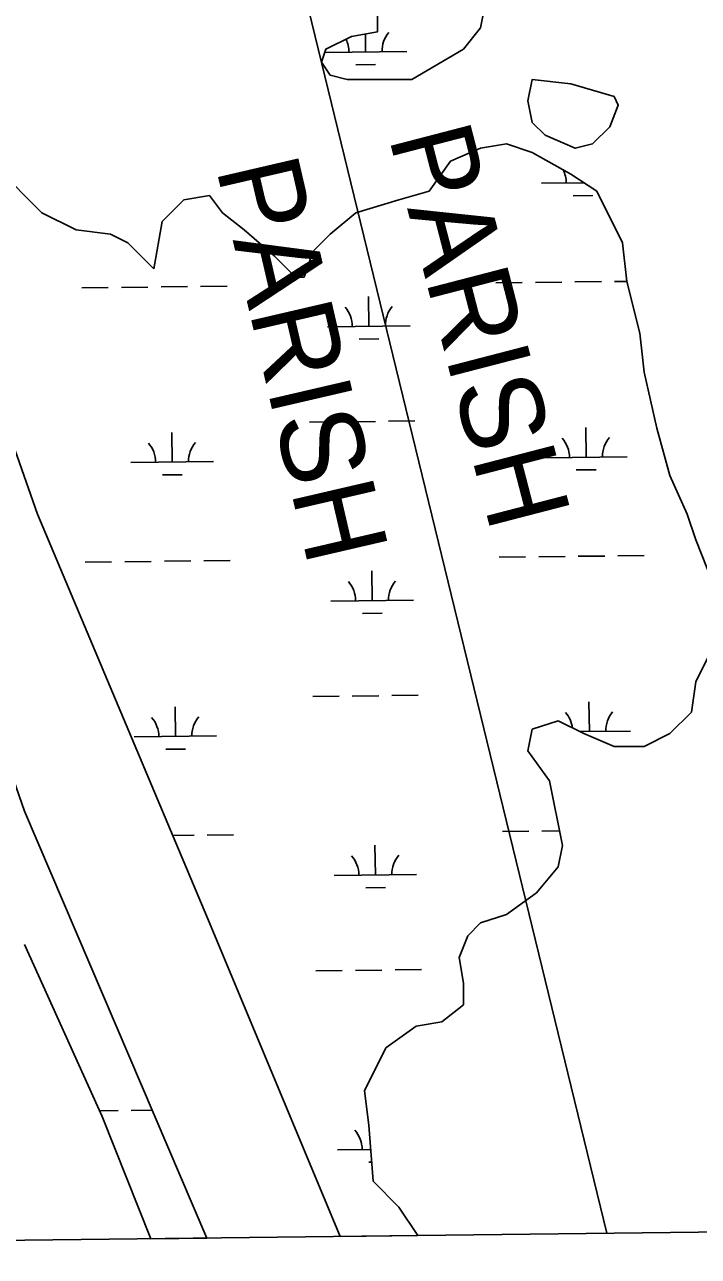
# Model space of a CAD drawing. Extents: x 3694830 to 3732949, y 415201 to 440970.
# Drawn here: x 3700698 to 3701515, y 420616 to 422110 of the extents above; entities that cross this region are included whole.
import ezdxf

# ---------------------------------------------------------------- set-up
doc = ezdxf.new("R2010")
doc.units = 0
for name, color, linetype in [('V-GRID-FRAM', 7, 'Continuous'), ('V-TOPO-BNDY', 7, 'Continuous'), ('V-TOPO-GNAM-IDEN', 7, 'Continuous'), ('V-TOPO-SHOR', 7, 'Continuous'), ('V-WETL-SWMP', 7, 'Continuous')]:
    doc.layers.add(name, color=color, linetype=linetype)

msp = doc.modelspace()

# ---------------------------------------------------------------- linework, layer by layer
at = {"layer": 'V-GRID-FRAM'}
msp.add_lwpolyline([(3698844.7, 438797.5), (3730590.8, 439176.2), (3730815.6, 420995.1), (3699053.6, 420616.3), (3698844.7, 438797.5)], dxfattribs=at)
at = {"layer": 'V-TOPO-BNDY'}
msp.add_line((3701404.1, 420644.3), (3699327.4, 429171.8), dxfattribs=at)
at = {"layer": 'V-TOPO-SHOR'}
for p, q in [((3700714, 421516.3), (3700537.1, 422017.2)), ((3701214.7, 421944.3), (3701251.2, 421959.9)), ((3701251.2, 421959.9), (3701282.5, 421965.2)), ((3701282.5, 421965.2), (3701313.8, 421954.7)), ((3701188.6, 421907.7), (3701214.7, 421944.3)), ((3701313.8, 421954.7), (3701360.7, 421928.6)), ((3700661.8, 421939.1), (3700719.2, 421881.7)), ((3701360.7, 421928.6), (3701392, 421907.7)), ((3700865.2, 421871.2), (3700891.3, 421897.3)), ((3700891.3, 421897.3), (3700922.6, 421902.5)), ((3700922.6, 421902.5), (3700938.2, 421881.7)), ((3701099.9, 421881.7), (3701152.1, 421897.3)), ((3701152.1, 421897.3), (3701188.6, 421907.7)), ((3701392, 421907.7), (3701423.3, 421845.1)), ((3700719.2, 421881.7), (3700760.9, 421860.8)), ((3700938.2, 421881.7), (3700964.3, 421860.8)), ((3701068.6, 421855.6), (3701099.9, 421881.7)), ((3700854.8, 421813.8), (3700865.2, 421871.2)), ((3700760.9, 421860.8), (3700802.6, 421855.6)), ((3700802.6, 421855.6), (3700823.5, 421845.1)), ((3700964.3, 421860.8), (3701000.8, 421829.5)), ((3701047.8, 421834.7), (3701068.6, 421855.6)), ((3700823.5, 421845.1), (3700854.8, 421813.8)), ((3701423.3, 421845.1), (3701428.5, 421798.2)), ((3701000.8, 421829.5), (3701026.9, 421803.4)), ((3701037.3, 421803.4), (3701047.8, 421834.7)), ((3701026.9, 421803.4), (3701037.3, 421803.4)), ((3701428.5, 421798.2), (3701444.2, 421735.5)), ((3701444.2, 421735.5), (3701449.4, 421688.6)), ((3701449.4, 421688.6), (3701465, 421620.7)), ((3700531.4, 421631.1), (3700698.3, 421156.2)), ((3701465, 421620.7), (3701480.7, 421563.3)), ((3701480.7, 421563.3), (3701501.5, 421516.3)), ((3700922.6, 421020.5), (3700714, 421516.3)), ((3701501.5, 421516.3), (3701512, 421485)), ((3701512, 421485), (3701532.8, 421432.8)), ((3701532.8, 421354.5), (3701512, 421312.8)), ((3701512, 421312.8), (3701506.8, 421276.3)), ((3701506.8, 421276.3), (3701480.7, 421250.2)), ((3701313.8, 421255.4), (3701308.6, 421229.3)), ((3701345.1, 421265.8), (3701313.8, 421255.4)), ((3701376.4, 421250.2), (3701345.1, 421265.8)), ((3701412.9, 421234.5), (3701376.4, 421250.2)), ((3701480.7, 421250.2), (3701449.4, 421234.5)), ((3701308.6, 421229.3), (3701334.6, 421192.7)), ((3701449.4, 421234.5), (3701412.9, 421234.5)), ((3701334.6, 421192.7), (3701350.3, 421114.5)), ((3700698.3, 421156.2), (3700919.3, 420638.5)), ((3701350.3, 421114.5), (3701345.1, 421088.4)), ((3701345.1, 421088.4), (3701319, 421057.1)), ((3701319, 421057.1), (3701282.5, 421031)), ((3701282.5, 421031), (3701251.2, 421020.5)), ((3701080.9, 420640.5), (3700922.6, 421020.5)), ((3701251.2, 421020.5), (3701235.5, 421004.9)), ((3701235.5, 421004.9), (3701225.1, 420978.8)), ((3700792.2, 420785.7), (3700698.3, 420994.4)), ((3701225.1, 420978.8), (3701230.3, 420947.5)), ((3701230.3, 420947.5), (3701230.3, 420921.4)), ((3701230.3, 420921.4), (3701204.2, 420900.5)), ((3701172.9, 420895.3), (3701136.4, 420869.2)), ((3701204.2, 420900.5), (3701172.9, 420895.3)), ((3701136.4, 420869.2), (3701110.4, 420817)), ((3701110.4, 420817), (3701115.6, 420775.2)), ((3700851.3, 420637.7), (3700792.2, 420785.7)), ((3701115.6, 420775.2), (3701120.8, 420707.4)), ((3701120.8, 420707.4), (3701152.1, 420676.1)), ((3701152.1, 420676.1), (3701175.1, 420641.6))]:
    msp.add_line(p, q, dxfattribs=at)
for points in [[(3701167.7, 422043.4), (3701089.5, 422043.4), (3701068.6, 422048.7), (3701058.2, 422064.3), (3701063.4, 422080), (3701094.7, 422095.6), (3701126, 422100.9), (3701126, 422147.8), (3701141.6, 422168.7), (3701167.7, 422179.1), (3701199, 422179.1), (3701251.2, 422158.3), (3701256.4, 422132.2), (3701251.2, 422106.1), (3701230.3, 422080)], [(3701360.7, 422038.2), (3701412.9, 422022.6), (3701418.1, 422012.1), (3701407.7, 421986), (3701386.8, 421965.2), (3701365.9, 421959.9), (3701329.4, 421975.6), (3701313.8, 421991.3), (3701308.6, 422017.3), (3701313.8, 422043.4)]]:
    msp.add_lwpolyline(points, close=True, dxfattribs=at)
at = {"layer": 'V-WETL-SWMP'}
for p, q in [((3701111.6, 422076.7), (3701111.4, 422098.4)), ((3701062.1, 422076.1), (3701161.6, 422077.3)), ((3701099.8, 422061.1), (3701123.8, 422061.4)), ((3700714, 421516.3), (3700537.1, 422017.2)), ((3701214.7, 421944.3), (3701251.2, 421959.9)), ((3701251.2, 421959.9), (3701282.5, 421965.2)), ((3701282.5, 421965.2), (3701313.8, 421954.7)), ((3701188.6, 421907.7), (3701214.7, 421944.3)), ((3701313.8, 421954.7), (3701360.7, 421928.6)), ((3700661.8, 421939.1), (3700719.2, 421881.7)), ((3701360.7, 421928.6), (3701392, 421907.7)), ((3701325, 421917.4), (3701376.6, 421918)), ((3701375, 421918), (3701375, 421919.1)), ((3700865.2, 421871.2), (3700891.3, 421897.3)), ((3700891.3, 421897.3), (3700922.6, 421902.5)), ((3700922.6, 421902.5), (3700938.2, 421881.7)), ((3701099.9, 421881.7), (3701152.1, 421897.3)), ((3701152.1, 421897.3), (3701188.6, 421907.7)), ((3701363.2, 421902.4), (3701387.2, 421902.7)), ((3701392, 421907.7), (3701423.3, 421845.1)), ((3700719.2, 421881.7), (3700760.9, 421860.8)), ((3700938.2, 421881.7), (3700964.3, 421860.8)), ((3701068.6, 421855.6), (3701099.9, 421881.7)), ((3700854.8, 421813.8), (3700865.2, 421871.2)), ((3700760.9, 421860.8), (3700802.6, 421855.6)), ((3700802.6, 421855.6), (3700823.5, 421845.1)), ((3700964.3, 421860.8), (3701000.8, 421829.5)), ((3701047.8, 421834.7), (3701068.6, 421855.6)), ((3700823.5, 421845.1), (3700854.8, 421813.8)), ((3701423.3, 421845.1), (3701428.5, 421798.2)), ((3701000.8, 421829.5), (3701026.9, 421803.4)), ((3701037.3, 421803.4), (3701047.8, 421834.7)), ((3700767.7, 421790.7), (3700799.7, 421791)), ((3700815.7, 421791.2), (3700847.7, 421791.6)), ((3700863.7, 421791.8), (3700895.7, 421792.2)), ((3700911.7, 421792.4), (3700943.7, 421792.8)), ((3701026.9, 421803.4), (3701037.3, 421803.4)), ((3701269.6, 421796.6), (3701301.6, 421797)), ((3701317.6, 421797.2), (3701349.6, 421797.6)), ((3701365.6, 421797.8), (3701397.6, 421798.2)), ((3701413.6, 421798.4), (3701428.5, 421798.5)), ((3701428.5, 421798.2), (3701444.2, 421735.5)), ((3701115.6, 421744.1), (3701115.2, 421780.1)), ((3701065.6, 421743.5), (3701165.6, 421744.7)), ((3701444.2, 421735.5), (3701449.4, 421688.6)), ((3701103.8, 421728.5), (3701127.8, 421728.8)), ((3701449.4, 421688.6), (3701465, 421620.7)), ((3700531.4, 421631.1), (3700698.3, 421156.2)), ((3701043.6, 421627.8), (3701075.6, 421628.1)), ((3701091.6, 421628.3), (3701123.6, 421628.7)), ((3701139.6, 421628.9), (3701171.6, 421629.3)), ((3700877.1, 421579.3), (3700876.7, 421615.3)), ((3701379, 421585.3), (3701378.6, 421621.3)), ((3701465, 421620.7), (3701480.7, 421563.3)), ((3701329, 421584.7), (3701429, 421585.9)), ((3700827.1, 421578.7), (3700927.1, 421579.9)), ((3701367.2, 421569.8), (3701391.2, 421570)), ((3700865.3, 421563.8), (3700889.3, 421564.1)), ((3701480.7, 421563.3), (3701501.5, 421516.3)), ((3700922.6, 421020.5), (3700714, 421516.3)), ((3701501.5, 421516.3), (3701512, 421485)), ((3701512, 421485), (3701532.8, 421432.8)), ((3701273.6, 421464), (3701305.6, 421464.4)), ((3701321.6, 421464.6), (3701353.6, 421464.9)), ((3701369.6, 421465.1), (3701401.6, 421465.5)), ((3701417.6, 421465.7), (3701449.6, 421466.1)), ((3700771.7, 421458), (3700803.7, 421458.4)), ((3700819.7, 421458.6), (3700851.7, 421459)), ((3700867.7, 421459.1), (3700899.7, 421459.5)), ((3700915.7, 421459.7), (3700947.7, 421460.1)), ((3701119.6, 421411.4), (3701119.2, 421447.4)), ((3701069.6, 421410.8), (3701169.6, 421412)), ((3701107.8, 421395.8), (3701131.8, 421396.1)), ((3701532.8, 421354.5), (3701512, 421312.8)), ((3701512, 421312.8), (3701506.8, 421276.3)), ((3701047.6, 421295.1), (3701079.6, 421295.5)), ((3701095.6, 421295.7), (3701127.6, 421296.1)), ((3701143.6, 421296.3), (3701175.6, 421296.6)), ((3701383, 421252.7), (3701382.5, 421288.7)), ((3700881.1, 421246.7), (3700880.7, 421282.7)), ((3701506.8, 421276.3), (3701480.7, 421250.2)), ((3701313.8, 421255.4), (3701308.6, 421229.3)), ((3701345.1, 421265.8), (3701313.8, 421255.4)), ((3701376.4, 421250.2), (3701345.1, 421265.8)), ((3701371.6, 421252.5), (3701432.9, 421253.3)), ((3700831.1, 421246.1), (3700931.1, 421247.3)), ((3701412.9, 421234.5), (3701376.4, 421250.2)), ((3701480.7, 421250.2), (3701449.4, 421234.5)), ((3700869.3, 421231.1), (3700893.3, 421231.4)), ((3701308.6, 421229.3), (3701334.6, 421192.7)), ((3701449.4, 421234.5), (3701412.9, 421234.5)), ((3701334.6, 421192.7), (3701350.3, 421114.5)), ((3700698.3, 421156.2), (3700919.3, 420638.5)), ((3700878, 421126.6), (3700903.7, 421126.9)), ((3700919.7, 421127.1), (3700951.7, 421127.5)), ((3701277.5, 421131.3), (3701309.5, 421131.7)), ((3701325.5, 421131.9), (3701346.7, 421132.2)), ((3701123.6, 421078.8), (3701123.1, 421114.8)), ((3701350.3, 421114.5), (3701345.1, 421088.4)), ((3701073.6, 421078.2), (3701173.6, 421079.4)), ((3701345.1, 421088.4), (3701319, 421057.1)), ((3701111.8, 421063.2), (3701135.8, 421063.5)), ((3701319, 421057.1), (3701282.5, 421031)), ((3701282.5, 421031), (3701251.2, 421020.5)), ((3701080.9, 420640.5), (3700922.6, 421020.5)), ((3701251.2, 421020.5), (3701235.5, 421004.9)), ((3701235.5, 421004.9), (3701225.1, 420978.8)), ((3700792.2, 420785.7), (3700698.3, 420994.4)), ((3701225.1, 420978.8), (3701230.3, 420947.5)), ((3701051.5, 420962.5), (3701083.5, 420962.8)), ((3701099.5, 420963), (3701131.5, 420963.4)), ((3701147.5, 420963.6), (3701179.5, 420964)), ((3701230.3, 420947.5), (3701230.3, 420921.4)), ((3701230.3, 420921.4), (3701204.2, 420900.5)), ((3701172.9, 420895.3), (3701136.4, 420869.2)), ((3701204.2, 420900.5), (3701172.9, 420895.3)), ((3701136.4, 420869.2), (3701110.4, 420817)), ((3701110.4, 420817), (3701115.6, 420775.2)), ((3700789, 420792.8), (3700811.6, 420793.1)), ((3700827.6, 420793.3), (3700853.1, 420793.6)), ((3700851.3, 420637.7), (3700792.2, 420785.7)), ((3701115.6, 420775.2), (3701120.8, 420707.4)), ((3701077.5, 420745.5), (3701117.8, 420746)), ((3701115.7, 420730.5), (3701119, 420730.6)), ((3701120.8, 420707.4), (3701152.1, 420676.1)), ((3701152.1, 420676.1), (3701175.1, 420641.6)), ((3701175.1, 420641.6), (3701080.9, 420640.5)), ((3700919.3, 420638.5), (3700851.3, 420637.7))]:
    msp.add_line(p, q, dxfattribs=at)
for points in [[(3701167.7, 422043.4), (3701089.5, 422043.4), (3701068.6, 422048.7), (3701058.2, 422064.3), (3701063.4, 422080), (3701094.7, 422095.6), (3701126, 422100.9), (3701126, 422147.8), (3701141.6, 422168.7), (3701167.7, 422179.1), (3701199, 422179.1), (3701251.2, 422158.3), (3701256.4, 422132.2), (3701251.2, 422106.1), (3701230.3, 422080)], [(3701360.7, 422038.2), (3701412.9, 422022.6), (3701418.1, 422012.1), (3701407.7, 421986), (3701386.8, 421965.2), (3701365.9, 421959.9), (3701329.4, 421975.6), (3701313.8, 421991.3), (3701308.6, 422017.3), (3701313.8, 422043.4)]]:
    msp.add_lwpolyline(points, close=True, dxfattribs=at)
for centre, start, end in [((3701056.4, 422076.5), 359.9115, 26.4792), ((3701166.8, 422077.8), 139.9115, 181.4552), ((3701319.8, 421917.8), 359.9115, 27.3387), ((3701060.4, 421743.9), 359.9115, 41.4552), ((3701170.9, 421745.2), 139.9115, 181.4552), ((3700821.9, 421579.2), 359.9115, 41.4552), ((3700932.3, 421580.5), 139.9115, 181.4552), ((3701323.7, 421585.1), 359.9115, 41.4552), ((3701434.2, 421586.5), 139.9115, 181.4552), ((3701064.4, 421411.2), 359.9115, 41.4552), ((3701174.8, 421412.5), 139.9115, 181.4552), ((3700825.8, 421246.5), 359.9115, 41.4552), ((3700936.3, 421247.8), 139.9115, 181.4552), ((3701327.7, 421252.5), 7.3667, 41.4552), ((3701438.2, 421253.8), 139.9115, 181.4552), ((3701068.3, 421078.6), 359.9115, 41.4552), ((3701178.8, 421079.9), 139.9115, 181.4552), ((3701072.3, 420745.9), 359.9115, 41.4552)]:
    msp.add_arc(centre, 35.2, start, end, dxfattribs=at)

# ---------------------------------------------------------------- texts
at = {"layer": 'V-TOPO-GNAM-IDEN'}
for rotation, p in [(284.5513, (3701139.5, 421973.6)), (283.072, (3700930.3, 421935.7))]:
    msp.add_text('PARISH', height=100, rotation=rotation, dxfattribs=at).set_placement(p)

doc.saveas('drawing.dxf')
